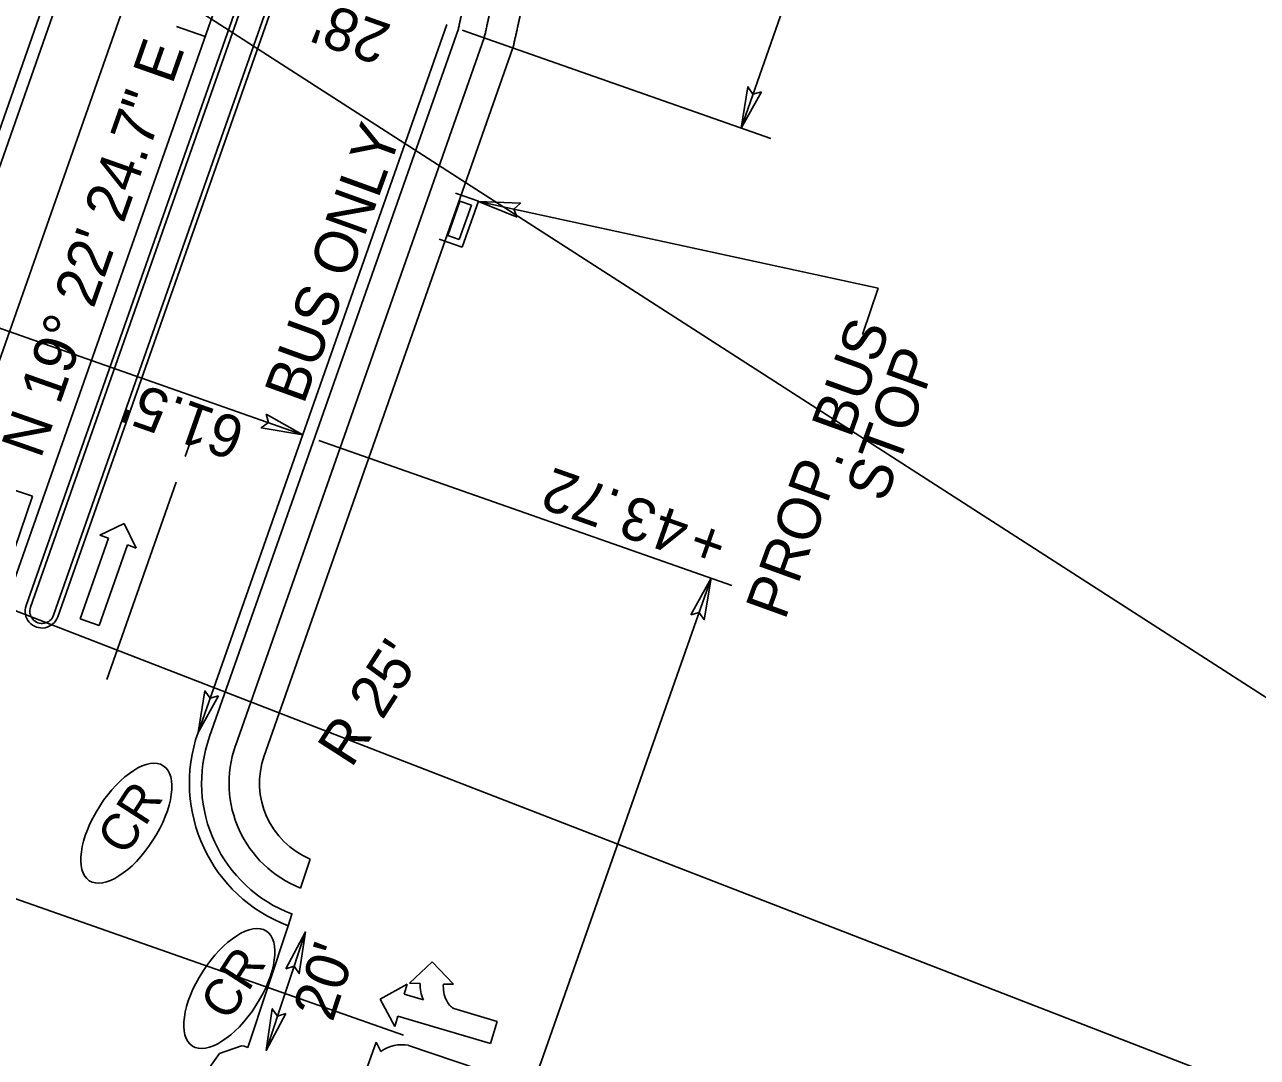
# Model space of a CAD drawing. Extents: x 1974386 to 1979988, y 776712 to 784860.
# Drawn here: x 1977395.6 to 1977597.8, y 780817.6 to 780987 of the extents above; entities that cross this region are included whole.
import ezdxf

# ---------------------------------------------------------------- set-up
doc = ezdxf.new("R2010")
doc.units = 0
for name, color, linetype in [('Old_Level_5', 7, 'Continuous'), ('Prop Conc 2ft 6in Curb and Gutter', 7, 'Continuous'), ('Prop Conc 4in Sidewalk', 7, 'Continuous'), ('Prop Conc 5in Monolithic Keyed In Island', 7, 'Continuous'), ('Prop Dimension', 7, 'Continuous'), ('Prop Dimension Text', 7, 'Continuous'), ('Prop EOT', 7, 'Continuous'), ('Prop Horizontal Alignment', 7, 'Continuous'), ('Prop Horizontal Alignment Direction Label', 7, 'Continuous'), ('Prop Horizontal Alignment Tick Small', 7, 'Continuous'), ('Prop Lane Arrow CELL', 7, 'Continuous'), ('Prop Lane Lines', 7, 'Continuous'), ('Prop Terminator CELL', 7, 'Continuous'), ('Prop WCC CELL', 7, 'Continuous'), ('Scratch_Level_1', 7, 'Continuous'), ('Sheet Layout Plan Border', 7, 'Continuous')]:
    doc.layers.add(name, color=color, linetype=linetype)

msp = doc.modelspace()

# ---------------------------------------------------------------- linework, layer by layer
at = {"layer": 'Old_Level_5'}
for p, q in [((1977464.97, 780952.41), (1977466.96, 780958.07)), ((1977470.02, 780958.03), (1977466.24, 780959.36)), ((1977466.96, 780958.07), (1977468.85, 780957.41)), ((1977467.36, 780950.49), (1977470.02, 780958.03)), ((1977468.85, 780957.41), (1977466.86, 780951.75)), ((1977463.59, 780951.81), (1977467.36, 780950.49)), ((1977466.86, 780951.75), (1977464.97, 780952.41))]:
    msp.add_line(p, q, dxfattribs=at)
at = {"layer": 'Prop Conc 2ft 6in Curb and Gutter'}
for p, q in [((1977366.39, 780898.48), (1977431.87, 781084.7)), ((1977425.89, 780870.24), (1977466.72, 780986.33)), ((1977439.42, 780841.1), (1977438.79, 780839.21))]:
    msp.add_line(p, q, dxfattribs=at)
msp.add_arc((1977447.6, 780862.62), 23, 160.6265, 249.39, dxfattribs=at)
msp.add_spline([(1977466.72, 780986.33), (1977466.86, 780986.99), (1977467.01, 780987.66), (1977467.16, 780988.32), (1977467.31, 780988.98), (1977467.45, 780989.65), (1977467.6, 780990.31), (1977467.75, 780990.98), (1977467.9, 780991.64), (1977468.04, 780992.31), (1977468.19, 780992.97), (1977468.34, 780993.63), (1977468.49, 780994.3), (1977468.64, 780994.96), (1977468.78, 780995.63), (1977468.93, 780996.29), (1977469.08, 780996.96), (1977469.23, 780997.62), (1977469.37, 780998.28), (1977469.52, 780998.95), (1977469.67, 780999.61), (1977469.82, 781000.28), (1977469.96, 781000.94), (1977470.11, 781001.61), (1977470.26, 781002.27), (1977470.41, 781002.94), (1977470.55, 781003.6), (1977470.7, 781004.26), (1977470.85, 781004.93), (1977471, 781005.59), (1977471.15, 781006.26), (1977471.29, 781006.92), (1977471.44, 781007.59), (1977471.59, 781008.25), (1977471.74, 781008.91), (1977471.88, 781009.58), (1977472.03, 781010.24), (1977472.18, 781010.91), (1977472.33, 781011.57), (1977472.47, 781012.24), (1977472.62, 781012.9), (1977472.77, 781013.56), (1977472.92, 781014.23), (1977473.06, 781014.89), (1977473.21, 781015.56), (1977473.36, 781016.22), (1977473.51, 781016.89), (1977473.66, 781017.55), (1977473.8, 781018.21), (1977473.95, 781018.88), (1977474.1, 781019.54), (1977474.25, 781020.21), (1977474.39, 781020.87), (1977474.54, 781021.54), (1977474.69, 781022.2), (1977474.84, 781022.86), (1977474.98, 781023.53), (1977475.13, 781024.19), (1977475.28, 781024.86), (1977475.43, 781025.52), (1977475.57, 781026.19), (1977475.72, 781026.85), (1977475.87, 781027.51), (1977476.02, 781028.18), (1977476.17, 781028.84), (1977476.31, 781029.51), (1977476.46, 781030.17), (1977476.61, 781030.84), (1977476.76, 781031.5), (1977476.9, 781032.16), (1977477.05, 781032.83), (1977477.2, 781033.49), (1977477.35, 781034.16), (1977477.49, 781034.82), (1977477.64, 781035.49)], degree=3, dxfattribs=at)
at = {"layer": 'Prop Conc 4in Sidewalk'}
for p, q in [((1977430.14, 780868.74), (1977470.96, 780984.83)), ((1977475.68, 780983.18), (1977434.79, 780866.89)), ((1977430.14, 780868.74), (1977430.15, 780868.76)), ((1977442.42, 780850.16), (1977440.84, 780845.4))]:
    msp.add_line(p, q, dxfattribs=at)
for radius, end in [(18.5, 248.5837), (13.5, 247.434)]:
    msp.add_arc((1977447.6, 780862.62), radius, 160.6265, end, dxfattribs=at)
for points in [[(1977470.96, 780984.83), (1977471.11, 780985.5), (1977471.26, 780986.16), (1977471.4, 780986.83), (1977471.55, 780987.49), (1977471.7, 780988.16), (1977471.85, 780988.82), (1977471.99, 780989.48), (1977472.14, 780990.15), (1977472.29, 780990.81), (1977472.44, 780991.48), (1977472.59, 780992.14), (1977472.73, 780992.81), (1977472.88, 780993.47), (1977473.03, 780994.13), (1977473.18, 780994.8), (1977473.32, 780995.46), (1977473.47, 780996.13), (1977473.62, 780996.79), (1977473.77, 780997.46), (1977473.91, 780998.12), (1977474.06, 780998.79), (1977474.21, 780999.45), (1977474.36, 781000.11), (1977474.5, 781000.78), (1977474.65, 781001.44), (1977474.8, 781002.11), (1977474.95, 781002.77), (1977475.1, 781003.44), (1977475.24, 781004.1), (1977475.39, 781004.76), (1977475.54, 781005.43), (1977475.69, 781006.09), (1977475.83, 781006.76), (1977475.98, 781007.42), (1977476.13, 781008.09), (1977476.28, 781008.75), (1977476.42, 781009.41), (1977476.57, 781010.08), (1977476.72, 781010.74), (1977476.87, 781011.41), (1977477.01, 781012.07), (1977477.16, 781012.74), (1977477.31, 781013.4), (1977477.46, 781014.06), (1977477.61, 781014.73), (1977477.75, 781015.39), (1977477.9, 781016.06), (1977478.05, 781016.72), (1977478.2, 781017.39), (1977478.34, 781018.05), (1977478.49, 781018.71), (1977478.64, 781019.38), (1977478.79, 781020.04), (1977478.93, 781020.71), (1977479.08, 781021.37), (1977479.23, 781022.04), (1977479.38, 781022.7), (1977479.52, 781023.36), (1977479.67, 781024.03), (1977479.82, 781024.69), (1977479.97, 781025.36), (1977480.12, 781026.02), (1977480.26, 781026.69), (1977480.41, 781027.35), (1977480.56, 781028.01), (1977480.71, 781028.68), (1977480.85, 781029.34), (1977481, 781030.01), (1977481.15, 781030.67), (1977481.3, 781031.34), (1977481.44, 781032), (1977481.59, 781032.67), (1977481.74, 781033.33), (1977481.89, 781033.99)], [(1977486.6, 781032.34), (1977486.46, 781031.67), (1977486.31, 781031.01), (1977486.16, 781030.34), (1977486.01, 781029.68), (1977485.87, 781029.01), (1977485.72, 781028.35), (1977485.57, 781027.68), (1977485.42, 781027.02), (1977485.27, 781026.36), (1977485.13, 781025.69), (1977484.98, 781025.03), (1977484.83, 781024.36), (1977484.68, 781023.7), (1977484.54, 781023.03), (1977484.39, 781022.37), (1977484.24, 781021.71), (1977484.09, 781021.04), (1977483.95, 781020.38), (1977483.8, 781019.71), (1977483.65, 781019.05), (1977483.5, 781018.38), (1977483.36, 781017.72), (1977483.21, 781017.06), (1977483.06, 781016.39), (1977482.91, 781015.73), (1977482.76, 781015.06), (1977482.62, 781014.4), (1977482.47, 781013.73), (1977482.32, 781013.07), (1977482.17, 781012.41), (1977482.03, 781011.74), (1977481.88, 781011.08), (1977481.73, 781010.41), (1977481.58, 781009.75), (1977481.44, 781009.08), (1977481.29, 781008.42), (1977481.14, 781007.76), (1977480.99, 781007.09), (1977480.85, 781006.43), (1977480.7, 781005.76), (1977480.55, 781005.1), (1977480.4, 781004.43), (1977480.25, 781003.77), (1977480.11, 781003.11), (1977479.96, 781002.44), (1977479.81, 781001.78), (1977479.66, 781001.11), (1977479.52, 781000.45), (1977479.37, 780999.78), (1977479.22, 780999.12), (1977479.07, 780998.46), (1977478.93, 780997.79), (1977478.78, 780997.13), (1977478.63, 780996.46), (1977478.48, 780995.8), (1977478.34, 780995.13), (1977478.19, 780994.47), (1977478.04, 780993.8), (1977477.89, 780993.14), (1977477.74, 780992.48), (1977477.6, 780991.81), (1977477.45, 780991.15), (1977477.3, 780990.48), (1977477.15, 780989.82), (1977477.01, 780989.15), (1977476.86, 780988.49), (1977476.71, 780987.83), (1977476.56, 780987.16), (1977476.42, 780986.5), (1977476.27, 780985.83), (1977476.12, 780985.17), (1977475.97, 780984.5), (1977475.83, 780983.84), (1977475.68, 780983.18)]]:
    msp.add_spline(points, degree=3, dxfattribs=at)
at = {"layer": 'Prop Conc 5in Monolithic Keyed In Island'}
for p, q in [((1977396.53, 780891.48), (1977462.63, 781079.46)), ((1977464.66, 781073.17), (1977400.3, 780890.15)), ((1977400.3, 780890.15), (1977400.3, 780890.15)), ((1977297.32, 780877.65), (1977457.7, 780821.25))]:
    msp.add_line(p, q, dxfattribs=at)
msp.add_arc((1977398.41, 780890.79), 2, 160.0989, 341.154, dxfattribs=at)
at = {"layer": 'Prop Dimension'}
for p, q in [((1977513.09, 780970.02), (1977546.3, 781064.48)), ((1977517.99, 780968.3), (1977467.35, 780986.1)), ((1977535.57, 780943.8), (1977532.99, 780936.19)), ((1977441.18, 780919.75), (1977383.17, 780940.15)), ((1977511.58, 780895), (1977443.83, 780918.82)), ((1977508.17, 780896.2), (1977448.46, 780726.39)), ((1977435.2, 780818.78), (1977441.62, 780838.19))]:
    msp.add_line(p, q, dxfattribs=at)
msp.add_lwpolyline([(1977470.01, 780958), (1977535.57, 780943.8)], dxfattribs=at)
at = {"layer": 'Prop EOT'}
for p, q in [((1977368.28, 780897.82), (1977433.76, 781084.03)), ((1977395.82, 780891.73), (1977461.91, 781079.68)), ((1977401.01, 780889.9), (1977465.36, 781072.92)), ((1977424.01, 780870.92), (1977464.83, 780986.99)), ((1977432.18, 780819.23), (1977438.79, 780839.21)), ((1977427.56, 780818.27), (1977431.14, 780819.52)), ((1977425.62, 780815.57), (1977427.56, 780818.27))]:
    msp.add_line(p, q, dxfattribs=at)
msp.add_lwpolyline([(1977431.14, 780819.52), (1977431.57, 780819.44), (1977432.18, 780819.23)], dxfattribs=at)
for centre, radius, start, end in [((1977398.41, 780890.79), 2.75, 160.0989, 341.154), ((1977447.6, 780862.62), 25, 160.6265, 249.39)]:
    msp.add_arc(centre, radius, start, end, dxfattribs=at)
at = {"layer": 'Prop Horizontal Alignment'}
msp.add_line((1977307.82, 780651.27), (1977457.11, 781075.82), dxfattribs=at)
at = {"layer": 'Prop Horizontal Alignment Tick Small'}
msp.add_line((1977425.18, 780985.03), (1977420.47, 780986.69), dxfattribs=at)
at = {"layer": 'Prop Lane Arrow CELL'}
for p, q in [((1977396.84, 780909.65), (1977393.72, 780910.72)), ((1977393.88, 780900.99), (1977396.84, 780909.65)), ((1977407.91, 780903.26), (1977411.88, 780905.2)), ((1977409.32, 780902.76), (1977407.91, 780903.26)), ((1977411.88, 780905.2), (1977413.85, 780901.16)), ((1977404.67, 780889.56), (1977409.32, 780902.76)), ((1977412.44, 780901.66), (1977407.78, 780888.46)), ((1977413.85, 780901.16), (1977412.44, 780901.66)), ((1977407.78, 780888.46), (1977404.67, 780889.56)), ((1977458.73, 780829.79), (1977462.41, 780833.32)), ((1977462.41, 780833.32), (1977465.94, 780829.64)), ((1977453.89, 780827.19), (1977458.34, 780829.66)), ((1977458.34, 780829.66), (1977457.85, 780828.01)), ((1977460.46, 780829.76), (1977458.73, 780829.79)), ((1977465.94, 780829.64), (1977464.27, 780829.66)), ((1977456.29, 780822.71), (1977453.89, 780827.19)), ((1977457.85, 780828.01), (1977460.99, 780827.08)), ((1977465.96, 780825.62), (1977473.07, 780823.53)), ((1977456.78, 780824.37), (1977456.29, 780822.71)), ((1977472, 780819.89), (1977456.78, 780824.37)), ((1977473.07, 780823.53), (1977472, 780819.89)), ((1977453.25, 780820.12), (1977451.56, 780815.35)), ((1977454, 780818.59), (1977453.25, 780820.12)), ((1977470.02, 780815.7), (1977458.53, 780819.6))]:
    msp.add_line(p, q, dxfattribs=at)
for centre, radius, start, end in [((1977465.56, 780829.33), 5.1, 175.1948, 206.0734), ((1977469.35, 780829.24), 5.1, 175.3136, 206.1672), ((1977467.46, 780828.11), 2.9, 202.6771, 238.9891), ((1977457.48, 780813.67), 6.04, 79.9274, 125.2391)]:
    msp.add_arc(centre, radius, start, end, dxfattribs=at)
at = {"layer": 'Prop Lane Lines'}
for p, q in [((1977421.9, 780916.15), (1977422.7, 780918.44)), ((1977409.05, 780879.6), (1977420.43, 780911.97))]:
    msp.add_line(p, q, dxfattribs=at)
at = {"layer": 'Prop Terminator CELL'}
for points in [[(1977516.42, 780976), (1977513.09, 780970.02), (1977514.21, 780976.82), (1977515.05, 780975.61)], [(1977476.36, 780955.44), (1977470.01, 780958), (1977476.89, 780957.74), (1977475.8, 780956.75)], [(1977435.2, 780923.09), (1977441.18, 780919.75), (1977434.38, 780920.87), (1977435.6, 780921.72)], [(1977504.83, 780890.21), (1977508.17, 780896.2), (1977507.05, 780889.4), (1977506.2, 780890.61)], [(1977427.35, 780876.9), (1977424.01, 780870.92), (1977425.13, 780877.72), (1977425.98, 780876.51)], [(1977438.4, 780832.15), (1977441.62, 780838.19), (1977440.63, 780831.37), (1977439.76, 780832.57)], [(1977438.42, 780824.83), (1977435.2, 780818.78), (1977436.19, 780825.6), (1977437.06, 780824.41)]]:
    msp.add_lwpolyline(points, close=True, dxfattribs=at)
at = {"layer": 'Prop WCC CELL'}
for centre in [(1977412.25, 780856.03), (1977429.15, 780828.92)]:
    msp.add_ellipse(centre, major_axis=(6.07, 9.43), ratio=0.462467, dxfattribs=at)
at = {"layer": 'Scratch_Level_1'}
msp.add_line((1977356.9, 780833.79), (1977516.04, 781286.37), dxfattribs=at)
at = {"layer": 'Sheet Layout Plan Border'}
for points in [[(1977881.86, 780701.89), (1978387.67, 782007.32), (1977408.59, 782386.68), (1976902.78, 781081.25)], [(1977111.11, 779526.05), (1977868.38, 780703.57), (1976985.24, 781271.52), (1976227.97, 780094)]]:
    msp.add_lwpolyline(points, close=True, dxfattribs=at)

# ---------------------------------------------------------------- texts
at = {"layer": 'Prop Dimension'}
for s, p in [('2', (1977487.05, 780912.75)), ('7', (1977492.04, 780910.99)), ('.', (1977493.81, 780910.37)), ('3', (1977499.84, 780908.25)), ('4', (1977505.14, 780906.38)), ('+', (1977511.38, 780904.19))]:
    msp.add_text(s, height=7, rotation=160.6265, dxfattribs=at).set_placement(p)
at = {"layer": 'Prop Dimension Text'}
for s, rotation, p in [("28'", 160.6265, (1977456.01, 780986.86)), ('BUS ONLY', 70.1136, (1977441.34, 780924.56)), ('PROP. BUS', 70.1136, (1977520.28, 780889.17)), ('STOP', 70.1136, (1977536.69, 780908.44)), ("61.5'", 160.6265, (1977432.13, 780922.02)), ("R 25'", 57.255, (1977449.16, 780864.92)), ("20'", 71.6828, (1977446.07, 780823.27))]:
    msp.add_text(s, height=7, rotation=rotation, dxfattribs=at).set_placement(p)
at = {"layer": 'Prop Horizontal Alignment Direction Label'}
msp.add_text('N 19%%d 22\' 24.7" E', height=7, rotation=70.6265, dxfattribs=at).set_placement((1977398.19, 780915.64))
at = {"layer": 'Prop WCC CELL'}
for p in [(1977412.18, 780850.47), (1977429.09, 780823.36)]:
    msp.add_text('CR', height=6, rotation=57.255, dxfattribs=at).set_placement(p)

doc.saveas('drawing.dxf')
